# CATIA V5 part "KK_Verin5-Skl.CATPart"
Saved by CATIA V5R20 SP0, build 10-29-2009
Part number: Verin5-Skl
Bounding box of the stored display mesh (mm): x -49.705 to -43.186, y -86.772 to -48.269, z 0 to 100
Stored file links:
  G:\Khaled_CFAO_2011\ST2M\ST2M_GR1\msallin\Khaled\Version_Finale\KK_Verin5-Skl.CATPart
  C:\Users\Mathieu\Desktop\Think Motion\JOUG-MELEE2.CATProduct
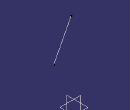
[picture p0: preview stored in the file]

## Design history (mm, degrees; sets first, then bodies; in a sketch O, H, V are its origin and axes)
Set1
  Point1: linked copy from another document
  Point2: linked copy from another document
Set2
  Line1: type PtPt, FirstPoint Point1, SecondPoint Point2
Body1 (main body)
